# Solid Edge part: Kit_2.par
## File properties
Sűrűség: 0,000 kg/m^3
Pontosság: 0,990
Author: bmolnar
Last saved by: bmolnar
Revision: 77
Username: bmolnar
Dokumentum tartalom típus: 0
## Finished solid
Body 1: solid body, 33 faces, 39 edges, 35 vertices, 2 separate solids.
  Faces by surface: plane 11, cone 10, cylinder 8, torus 4
  Edges by curve: circle 31, line 8
Bounding box of the edges (mm; curved faces can reach further): 19.000 x 18.450 x 3.100, from (-9.5, -9.5, 48.6) to (9.5, 8.95, 51.7).
Cylindrical faces by radius (mm): R4.21 x1, R4.6 x1, R5.68 x1, R5.75 x1, R6.6 x1, R8.5 x1, R8.95 x1, R9.5 x1
Conical faces (half-angle, radius in mm at the cone's reference point): 3 deg R5.715 x1, 7 deg R5.2386 x1, 14 deg R4.105 x1, 14 deg R4.3042 x1, 17 deg R4.105 x1, 23 deg R4.6448 x1, 42.5 deg R4.0959 x1, 45 deg R4.75 x1, 45 deg R6.45 x1, 87 deg R4.0979 x1
Toroidal faces (ring radius, tube radius in mm): R4.5656 r0.1575 x1, R4.974 r0.2275 x1, R5.48 r0.2 x1, R7 r0.4 x1
Planar faces by outward normal: +z 4, -z 5, oblique 2
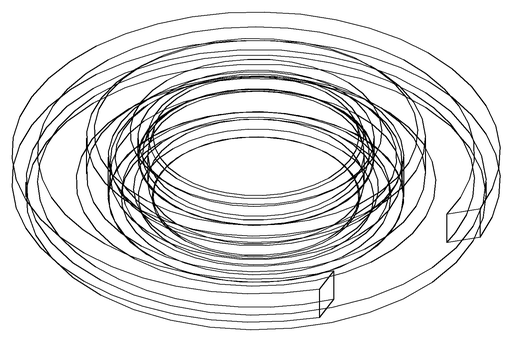
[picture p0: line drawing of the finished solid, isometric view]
